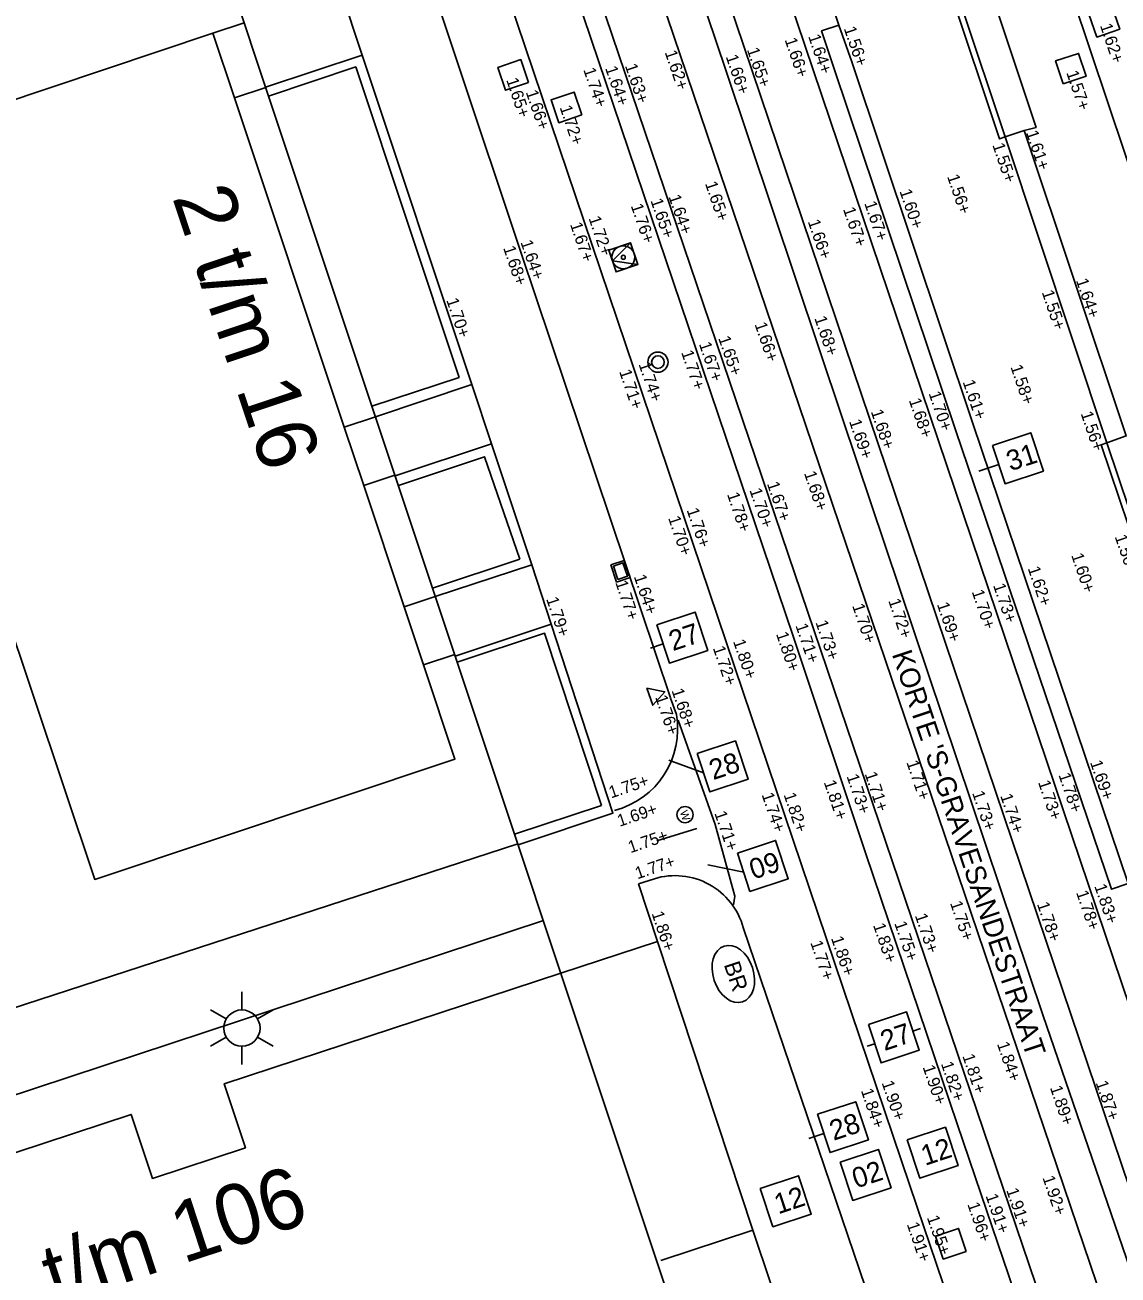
# Model space of a CAD drawing. Extents: x 122462 to 123306, y 485548 to 486417.
# Drawn here: x 122805.01 to 122832.11, y 486111.75 to 486142.72 of the extents above; entities that cross this region are included whole.
import ezdxf

# ---------------------------------------------------------------- set-up
doc = ezdxf.new("R2010")
doc.units = 0
for name, color, linetype in [('B nummers', 7, 'Continuous'), ('B-WE-AL-WERKGRENS-G', 7, 'Continuous'), ('B-WE-IE-MEUBILAIR_WEGMEUBILAIR-S', 7, 'Continuous'), ('B-WE-IE-MEUBILAIR_WEGMEUBILAIR_VERKEERSBORD-S', 7, 'Continuous'), ('B-WE-IE-TERREINAFSCHEIDING_KUNSTMATIG_HEKWERK-G', 7, 'Continuous'), ('B-WE-OG-HOOGTEPUNT-S', 7, 'Continuous'), ('B-WE-OG-TOPOGRAFIE_STRAATNAAM', 7, 'Continuous'), ('B-WE-OG-TOPOKAART-G', 7, 'Continuous'), ('B-WE-VH-KANTOPSLUITING_OPSLUITBAND_100X200-G', 7, 'Continuous'), ('B-WE-VH-KANTOPSLUITING_TROTTOIRBAND_180 200-G', 7, 'Continuous'), ('B-WE-VH-MATERIAALGRENS-G', 7, 'Continuous'), ('B-WE-VW-MARKERING_LANGS_STREEP_DOORGETROKKEN_010-G', 7, 'Continuous'), ('Level 1', 7, 'Continuous'), ('Level 17', 7, 'Continuous'), ('Level 4', 7, 'Continuous'), ('Level 50', 7, 'Continuous'), ('Level 58', 7, 'Continuous'), ('V Inritband 100x50', 7, 'Continuous'), ('V materiaalscheiding algemeen', 7, 'Continuous'), ('V meubilair trammast', 7, 'Continuous'), ('V Rails', 7, 'Continuous'), ('V riool putdeksel', 7, 'Continuous'), ('V riool trottoirkolk', 7, 'Continuous'), ('V RWS-band 115-225x250 mm specie', 7, 'Continuous'), ('V trottoirband 130-150x250 mm specie', 7, 'Continuous'), ('V trottoirband 180-200x250 mm specie', 7, 'Continuous')]:
    doc.layers.add(name, color=color, linetype=linetype)

msp = doc.modelspace()

# ---------------------------------------------------------------- linework, layer by layer
at = {"layer": 'B nummers'}
for p, q in [((122829.154, 486131.83), (122828.664, 486131.668)), ((122820.832, 486127.388), (122820.518, 486127.283)), ((122821.832, 486124.193), (122820.973, 486124.506)), ((122822.83, 486121.728), (122821.939, 486121.912)), ((122827.028, 486117.793), (122827.216, 486117.855)), ((122826.078, 486117.479), (122825.89, 486117.417)), ((122824.816, 486115.255), (122824.449, 486115.134))]:
    msp.add_line(p, q, dxfattribs=at)
for points in [[(122828.997, 486132.305), (122829.947, 486132.618), (122830.26, 486131.668), (122829.311, 486131.355)], [(122820.676, 486127.863), (122821.625, 486128.176), (122821.939, 486127.227), (122820.989, 486126.913)], [(122821.675, 486124.667), (122822.625, 486124.981), (122822.938, 486124.031), (122821.989, 486123.718)], [(122822.673, 486122.203), (122823.623, 486122.516), (122823.936, 486121.566), (122822.986, 486121.253)], [(122825.921, 486117.954), (122826.871, 486118.267), (122827.184, 486117.318), (122826.235, 486117.004)], [(122824.659, 486115.73), (122825.609, 486116.043), (122825.922, 486115.094), (122824.973, 486114.78)], [(122826.882, 486115.094), (122827.831, 486115.408), (122828.145, 486114.458), (122827.195, 486114.145)], [(122825.22, 486114.546), (122826.17, 486114.859), (122826.483, 486113.91), (122825.533, 486113.596)], [(122823.243, 486113.894), (122824.193, 486114.207), (122824.506, 486113.257), (122823.556, 486112.944)]]:
    msp.add_lwpolyline(points, close=True, dxfattribs=at)
at = {"layer": 'B-WE-AL-WERKGRENS-G'}
msp.add_lwpolyline([(122857.632, 486078.279), (122830.484, 486160.606), (122900.937, 486183.81), (122887.855, 486222.555), (122665.445, 486149.273), (122678.196, 486110.449), (122807.072, 486152.895), (122835.324, 486068.154)], dxfattribs=at)
at = {"layer": 'B-WE-IE-MEUBILAIR_WEGMEUBILAIR-S'}
for centre, radius in [((122820.704, 486134.369), 0.25), ((122820.704, 486134.369), 0.156), ((122821.377, 486123.156), 0.2)]:
    msp.add_circle(centre, radius, dxfattribs=at)
msp.add_ellipse((122822.574, 486119.207), major_axis=(-0.229, 0.692), ratio=0.685994, dxfattribs=at)
at = {"layer": 'B-WE-IE-MEUBILAIR_WEGMEUBILAIR_VERKEERSBORD-S'}
for points in [[(122819.485, 486137.145), (122819.668, 486136.605), (122820.208, 486136.788), (122820.025, 486137.328)], [(122820.025, 486137.328), (122819.576, 486136.875), (122820.208, 486136.788)]]:
    msp.add_lwpolyline(points, close=True, dxfattribs=at)
for radius in [0.285, 0.0487]:
    msp.add_circle((122819.846, 486136.967), radius, dxfattribs=at)
at = {"layer": 'B-WE-IE-TERREINAFSCHEIDING_KUNSTMATIG_HEKWERK-G'}
for points in [[(122811.05, 486140.963), (122813.212, 486141.684), (122815.779, 486133.985)], [(122813.614, 486133.274), (122815.779, 486133.985)], [(122814.268, 486131.313), (122816.408, 486132.026), (122817.279, 486129.489)], [(122815.115, 486128.77), (122817.279, 486129.489)], [(122815.726, 486126.937), (122817.895, 486127.652), (122819.303, 486123.38)], [(122817.149, 486122.67), (122819.303, 486123.38)]]:
    msp.add_lwpolyline(points, dxfattribs=at)
at = {"layer": 'B-WE-OG-TOPOKAART-G'}
msp.add_lwpolyline([(122818.297, 486119.225), (122820.692, 486120.01), (122823.056, 486112.856), (122820.776, 486112.107)], dxfattribs=at)
at = {"layer": 'B-WE-VH-KANTOPSLUITING_OPSLUITBAND_100X200-G'}
for points in [[(122810.978, 486141.18), (122813.375, 486141.976), (122816.092, 486133.815), (122813.7, 486133.014)], [(122814.188, 486131.55), (122816.581, 486132.347), (122817.579, 486129.349), (122815.184, 486128.562)], [(122815.678, 486127.082), (122818.058, 486127.875), (122819.588, 486123.196), (122817.236, 486122.408)], [(122818.058, 486127.875), (122818.058, 486127.875), (122818.058, 486127.875)], [(122823.056, 486112.856), (122825.309, 486106.161)]]:
    msp.add_lwpolyline(points, dxfattribs=at)
at = {"layer": 'B-WE-VH-KANTOPSLUITING_TROTTOIRBAND_180 200-G'}
for points in [[(122828.719, 486113.742), (122831.584, 486105.321)], [(122839.772, 486076.05), (122830.973, 486102.107), (122827.132, 486113.429)]]:
    msp.add_lwpolyline(points, dxfattribs=at)
at = {"layer": 'B-WE-VH-MATERIAALGRENS-G'}
for p, q in [((122817.579, 486129.349), (122818.058, 486127.875)), ((122820.692, 486120.01), (122820.224, 486121.438))]:
    msp.add_line(p, q, dxfattribs=at)
for points in [[(122812.82, 486143.569), (122812.844, 486143.577), (122813.375, 486141.976)], [(122816.092, 486133.815), (122816.581, 486132.347)]]:
    msp.add_lwpolyline(points, dxfattribs=at)
at = {"layer": 'B-WE-VW-MARKERING_LANGS_STREEP_DOORGETROKKEN_010-G'}
for points in [[(122842.379, 486082.508), (122834.669, 486105.323), (122830.244, 486118.192), (122825.281, 486132.973), (122822.384, 486141.602), (122818.71, 486152.508)], [(122821.667, 486122.81), (122820.679, 486122.506)]]:
    msp.add_lwpolyline(points, dxfattribs=at)
at = {"layer": 'Level 1'}
for p, q in [((122809.671, 486142.52), (122810.206, 486140.916)), ((122810.206, 486140.916), (122812.928, 486132.755)), ((122812.928, 486132.755), (122813.41, 486131.309)), ((122813.41, 486131.309), (122814.413, 486128.303)), ((122814.413, 486128.303), (122814.891, 486126.869))]:
    msp.add_line(p, q, dxfattribs=at)
for points in [[(122810.445, 486142.778), (122809.671, 486142.52)], [(122814.891, 486126.869), (122815.67, 486124.529), (122806.739, 486121.552), (122804.466, 486128.366)], [(122797.378, 486110.742), (122796.9, 486112.191), (122807.647, 486115.728), (122808.17, 486114.142), (122810.476, 486114.9), (122809.951, 486116.489), (122818.297, 486119.226)]]:
    msp.add_lwpolyline(points, dxfattribs=at)
at = {"layer": 'Level 17'}
for points in [[(122810.98, 486141.173), (122810.206, 486140.916)], [(122812.928, 486132.755), (122813.7, 486133.015)], [(122813.41, 486131.309), (122814.184, 486131.564)], [(122815.185, 486128.562), (122814.413, 486128.303)], [(122814.891, 486126.869), (122815.665, 486127.122)], [(122817.228, 486122.432), (122802.475, 486117.637), (122801.542, 486120.472)], [(122647.924, 486072.158), (122651.346, 486073.253), (122652.967, 486073.352), (122655.638, 486071.965), (122657.005, 486072.23), (122676.116, 486078.506), (122677.711, 486079.03), (122678.168, 486077.696), (122713.768, 486089.314), (122724.595, 486088.498), (122776.007, 486105.316), (122795.628, 486111.735), (122795.201, 486113.055), (122817.863, 486120.529)]]:
    msp.add_lwpolyline(points, dxfattribs=at)
at = {"layer": 'Level 4'}
msp.add_line((122797.541, 486138.474), (122809.671, 486142.52), dxfattribs=at)
at = {"layer": 'Level 50'}
for p, q in [((122810.389, 486118.317), (122810.389, 486118.767)), ((122809.999, 486118.092), (122809.609, 486118.317)), ((122811.168, 486118.317), (122810.778, 486118.092)), ((122809.999, 486117.642), (122809.609, 486117.417)), ((122811.168, 486117.417), (122810.778, 486117.642)), ((122810.389, 486116.967), (122810.389, 486117.417))]:
    msp.add_line(p, q, dxfattribs=at)
msp.add_circle((122810.389, 486117.867), 0.45, dxfattribs=at)
at = {"layer": 'V Inritband 100x50'}
for points in [[(122832.367, 486121.446), (122831.947, 486121.305), (122828.09, 486132.668), (122825.079, 486141.609), (122824.762, 486142.578), (122825.19, 486142.715)], [(122832.367, 486121.446), (122828.514, 486132.846), (122825.512, 486141.812), (122825.19, 486142.715)], [(122831.838, 486132.366), (122832.314, 486132.542), (122829.781, 486140.105), (122829.312, 486139.948), (122831.838, 486132.366)]]:
    msp.add_lwpolyline(points, dxfattribs=at)
at = {"layer": 'V materiaalscheiding algemeen'}
for points in [[(122829.312, 486139.948), (122829.17, 486139.9), (122821.692, 486162.285)], [(122829.781, 486140.105), (122830.081, 486140.185), (122823.529, 486159.849)], [(122835.041, 486122.41), (122831.696, 486132.317), (122831.838, 486132.366)], [(122821.208, 486125.493), (122822.126, 486122.911), (122822.614, 486121.138), (122822.576, 486120.917)]]:
    msp.add_lwpolyline(points, dxfattribs=at)
at = {"layer": 'V meubilair trammast'}
msp.add_lwpolyline([(122820.431, 486126.292), (122820.575, 486125.866), (122820.873, 486126.203)], close=True, dxfattribs=at)
at = {"layer": 'V Rails'}
for p, q in [((122819.673, 486156.047), (122836.339, 486106.728)), ((122818.309, 486155.586), (122834.974, 486106.268)), ((122817.744, 486152.354), (122833.474, 486105.961)), ((122816.38, 486151.892), (122832.11, 486105.5))]:
    msp.add_line(p, q, dxfattribs=at)
at = {"layer": 'V riool putdeksel'}
for points in [[(122831.39, 486142.988), (122831.59, 486142.422), (122832.156, 486142.622), (122831.956, 486143.188)], [(122817.497, 486141.297), (122817.305, 486141.865), (122816.737, 486141.673), (122816.929, 486141.105)], [(122830.752, 486141.262), (122831.321, 486141.451), (122831.132, 486142.02), (122830.563, 486141.831)], [(122818.816, 486140.493), (122818.624, 486141.061), (122818.056, 486140.869), (122818.248, 486140.301)], [(122828.347, 486112.333), (122828.158, 486112.902), (122827.588, 486112.712), (122827.778, 486112.143)]]:
    msp.add_lwpolyline(points, close=True, dxfattribs=at)
at = {"layer": 'V riool trottoirkolk'}
for p, q in [((122819.537, 486129.346), (122819.869, 486129.457)), ((122819.869, 486129.457), (122820.012, 486129.031)), ((122819.874, 486129.396), (122819.889, 486129.351)), ((122819.885, 486129.41), (122819.88, 486129.408)), ((122819.681, 486128.919), (122819.537, 486129.346)), ((122819.889, 486129.351), (122819.899, 486129.32)), ((122819.917, 486129.315), (122819.912, 486129.314)), ((122819.914, 486129.277), (122819.939, 486129.201)), ((122819.925, 486129.292), (122819.92, 486129.29)), ((122819.957, 486129.197), (122819.952, 486129.195)), ((122819.954, 486129.159), (122819.979, 486129.083)), ((122819.965, 486129.173), (122819.96, 486129.171)), ((122819.996, 486129.078), (122819.992, 486129.077)), ((122820.012, 486129.031), (122819.681, 486128.919))]:
    msp.add_line(p, q, dxfattribs=at)
msp.add_lwpolyline([(122819.712, 486128.983), (122819.601, 486129.315), (122819.838, 486129.394), (122819.949, 486129.062)], close=True, dxfattribs=at)
for centre, start, end in [((122819.884, 486129.399), 108.5509, 198.5509), ((122819.909, 486129.323), 198.5509, 288.5509), ((122819.923, 486129.28), 108.5509, 198.5509), ((122819.949, 486129.205), 198.5509, 288.5509), ((122819.963, 486129.162), 108.5509, 198.5509), ((122819.989, 486129.086), 198.5509, 288.5509)]:
    msp.add_arc(centre, 0.01, start, end, dxfattribs=at)
at = {"layer": 'V RWS-band 115-225x250 mm specie'}
msp.add_lwpolyline([(122818.364, 486163.338), (122821.173, 486154.804), (122825.19, 486142.715)], dxfattribs=at)
at = {"layer": 'V trottoirband 130-150x250 mm specie'}
msp.add_line((122820.224, 486121.438), (122820.618, 486121.567), dxfattribs=at)
for points in [[(122821.014, 486126.043), (122821.162, 486125.639)], [(122822.821, 486120.359), (122829.02, 486102.127)]]:
    msp.add_lwpolyline(points, dxfattribs=at)
for centre, radius, start, end in [((122819.11, 486125.278), 2.083, 284.3363, 9.9671), ((122821.126, 486119.884), 1.76, 15.6603, 106.8227)]:
    msp.add_arc(centre, radius, start, end, dxfattribs=at)
at = {"layer": 'V trottoirband 180-200x250 mm specie'}
for points in [[(122834.911, 486138.929), (122832.725, 486138.213), (122824.045, 486164.077)], [(122829.312, 486139.948), (122821.835, 486162.331)], [(122809.854, 486159.259), (122810.231, 486158.325), (122812.595, 486151.199), (122817.313, 486137.073), (122821.012, 486126.049)], [(122822.606, 486126.825), (122813.268, 486154.44)], [(122817.192, 486147.874), (122824.061, 486127.577)], [(122835.198, 486122.386), (122831.838, 486132.366)], [(122824.061, 486127.577), (122825.861, 486122.186), (122828.124, 486115.492), (122828.719, 486113.742)], [(122827.132, 486113.429), (122826.743, 486114.577), (122822.606, 486126.825)]]:
    msp.add_lwpolyline(points, dxfattribs=at)

# ---------------------------------------------------------------- texts
at = {"layer": 'B nummers'}
for s, p in [('31', (122829.443, 486131.662)), ('27', (122821.074, 486127.205)), ('28', (122822.073, 486124.009)), ('09', (122823.071, 486121.544)), ('27', (122826.32, 486117.296)), ('28', (122825.058, 486115.072)), ('12', (122827.327, 486114.452)), ('02', (122825.618, 486113.888)), ('12', (122823.688, 486113.251))]:
    msp.add_text(s, height=0.5, rotation=18.2603, dxfattribs=at).set_placement(p)
at = {"layer": 'B-WE-IE-MEUBILAIR_WEGMEUBILAIR-S'}
for s, height, p in [('W', 0.2, (122821.243, 486123.224)), ('BR', 0.4, (122822.335, 486119.442))]:
    msp.add_text(s, height=height, rotation=288.2859, dxfattribs=at).set_placement(p)
at = {"layer": 'B-WE-OG-HOOGTEPUNT-S'}
for s, rotation, p in [('1.56+', 288.6561, (122825.309, 486142.637)), ('1.62+', 288.5518, (122831.661, 486142.712)), ('1.66+', 288.6561, (122823.843, 486142.359)), ('1.64+', 288.6561, (122824.426, 486142.443)), ('1.62+', 288.7047, (122820.869, 486142.048)), ('1.65+', 288.6561, (122822.907, 486142.114)), ('1.63+', 288.7047, (122819.882, 486141.715)), ('1.66+', 288.6561, (122822.382, 486141.94)), ('1.74+', 288.7047, (122818.851, 486141.615)), ('1.64+', 288.7047, (122819.392, 486141.655)), ('1.57+', 288.5518, (122830.826, 486141.543)), ('1.65+', 288.5509, (122816.939, 486141.363)), ('1.66+', 288.7047, (122817.423, 486141.061)), ('1.72+', 288.5509, (122818.265, 486140.682)), ('1.61+', 288.5518, (122829.827, 486140.061)), ('1.55+', 288.5518, (122828.993, 486139.751)), ('1.56+', 288.6561, (122827.869, 486138.971)), ('1.65+', 288.7047, (122821.868, 486138.797)), ('1.65+', 288.7047, (122820.516, 486138.374)), ('1.64+', 288.7047, (122820.963, 486138.471)), ('1.67+', 288.6561, (122825.816, 486138.308)), ('1.60+', 288.6561, (122826.69, 486138.606)), ('1.76+', 288.7047, (122820.028, 486138.245)), ('1.67+', 288.6561, (122825.29, 486138.16)), ('1.67+', 288.7047, (122818.521, 486137.784)), ('1.72+', 288.7047, (122818.98, 486137.937)), ('1.66+', 288.6561, (122824.416, 486137.855)), ('1.68+', 288.5509, (122816.864, 486137.201)), ('1.64+', 288.5509, (122817.293, 486137.344)), ('1.64+', 288.5518, (122831.065, 486136.394)), ('1.70+', 288.5509, (122815.454, 486135.907)), ('1.55+', 288.5518, (122830.217, 486136.103)), ('1.66+', 288.7047, (122823.097, 486135.309)), ('1.68+', 288.7047, (122824.579, 486135.46)), ('1.65+', 288.7047, (122822.196, 486134.966)), ('1.77+', 288.7047, (122821.277, 486134.613)), ('1.67+', 288.7047, (122821.718, 486134.82)), ('1.74+', 288.7047, (122820.22, 486134.32)), ('1.71+', 288.7047, (122819.739, 486134.137)), ('1.58+', 288.8218, (122829.44, 486134.252)), ('1.61+', 288.5604, (122828.256, 486133.882)), ('1.68+', 288.5604, (122826.922, 486133.426)), ('1.70+', 288.5604, (122827.412, 486133.597)), ('1.68+', 288.5604, (122825.979, 486133.146)), ('1.56+', 288.5604, (122831.182, 486133.098)), ('1.69+', 288.5604, (122825.439, 486132.903)), ('1.68+', 288.5604, (122824.323, 486131.619)), ('1.70+', 288.5604, (122822.971, 486131.197)), ('1.67+', 288.5604, (122823.403, 486131.358)), ('1.78+', 288.5604, (122822.415, 486131.094)), ('1.76+', 288.7047, (122821.413, 486130.705)), ('1.70+', 288.7047, (122820.954, 486130.507)), ('1.56+', 288.8218, (122832.026, 486130.045)), ('1.60+', 288.8218, (122830.947, 486129.585)), ('1.64+', 288.1445, (122820.104, 486129.057)), ('1.62+', 288.5604, (122829.871, 486129.259)), ('1.77+', 288.1445, (122819.644, 486128.912)), ('1.73+', 288.5604, (122829.011, 486128.838)), ('1.79+', 288.1445, (122817.931, 486128.502)), ('1.72+', 288.5604, (122826.412, 486128.459)), ('1.70+', 288.5604, (122828.482, 486128.682)), ('1.70+', 288.5604, (122825.517, 486128.334)), ('1.69+', 288.5604, (122827.617, 486128.37)), ('1.71+', 288.5604, (122824.11, 486127.845)), ('1.73+', 288.5604, (122824.607, 486127.923)), ('1.80+', 288.5604, (122823.629, 486127.635)), ('1.72+', 288.5604, (122822.063, 486127.287)), ('1.80+', 288.5604, (122822.564, 486127.45)), ('1.68+', 288.5509, (122821.038, 486126.233)), ('1.76+', 288.5509, (122820.633, 486126.066)), ('1.71+', 288.5604, (122826.862, 486124.451)), ('1.69+', 288.5604, (122831.414, 486124.453)), ('1.73+', 288.5604, (122825.377, 486124.11)), ('1.71+', 288.5604, (122825.827, 486124.167)), ('1.78+', 288.5604, (122830.632, 486124.142)), ('1.75+', 18.5365, (122819.544, 486123.557)), ('1.81+', 288.5604, (122824.813, 486123.961)), ('1.73+', 288.5604, (122830.126, 486123.958)), ('1.74+', 288.5604, (122823.272, 486123.652)), ('1.82+', 288.5604, (122823.816, 486123.652)), ('1.73+', 288.5604, (122828.491, 486123.695)), ('1.74+', 288.5604, (122829.188, 486123.624)), ('1.69+', 18.5365, (122819.754, 486122.852)), ('1.71+', 288.6634, (122822.1, 486123.194)), ('1.75+', 18.5365, (122820.021, 486122.198)), ('1.77+', 18.5365, (122820.196, 486121.553)), ('1.83+', 288.8218, (122831.519, 486121.386)), ('1.75+', 288.5604, (122827.944, 486120.966)), ('1.78+', 288.6561, (122831.068, 486121.227)), ('1.86+', 288.1445, (122820.543, 486120.713)), ('1.73+', 288.5604, (122827.071, 486120.658)), ('1.78+', 288.6561, (122830.098, 486120.942)), ('1.83+', 288.5604, (122826.035, 486120.417)), ('1.75+', 288.5604, (122826.562, 486120.464)), ('1.86+', 288.5604, (122824.993, 486120.095)), ('1.77+', 288.5604, (122824.479, 486119.986)), ('1.84+', 288.5604, (122829.107, 486117.477)), ('1.82+', 288.5604, (122827.717, 486116.987)), ('1.81+', 288.5604, (122828.248, 486117.177)), ('1.90+', 288.5604, (122827.265, 486116.901)), ('1.84+', 288.5604, (122825.734, 486116.32)), ('1.90+', 288.5604, (122826.247, 486116.513)), ('1.89+', 288.6561, (122830.421, 486116.392)), ('1.87+', 288.6561, (122831.553, 486116.513)), ('1.92+', 288.6561, (122830.235, 486114.16)), ('1.91+', 288.6561, (122829.336, 486113.852)), ('1.91+', 288.6561, (122828.824, 486113.712)), ('1.96+', 288.6561, (122828.372, 486113.501)), ('1.91+', 288.6561, (122826.871, 486113.007)), ('1.95+', 288.6561, (122827.369, 486113.175))]:
    msp.add_text(s, height=0.3, rotation=rotation, dxfattribs=at).set_placement(p)
at = {"layer": 'B-WE-OG-TOPOGRAFIE_STRAATNAAM'}
msp.add_text("KORTE 'S-GRAVESANDESTRAAT", height=0.5, rotation=288.5109, dxfattribs=at).set_placement((122826.5, 486127.135))
at = {"layer": 'Level 58'}
for s, rotation, p in [('2 t/m 16', 288.4455, (122808.656, 486138.458)), ('86 t/m 106', 18.194, (122803.109, 486110.111))]:
    msp.add_text(s, height=1.5, rotation=rotation, dxfattribs=at).set_placement(p)

doc.saveas('drawing.dxf')
